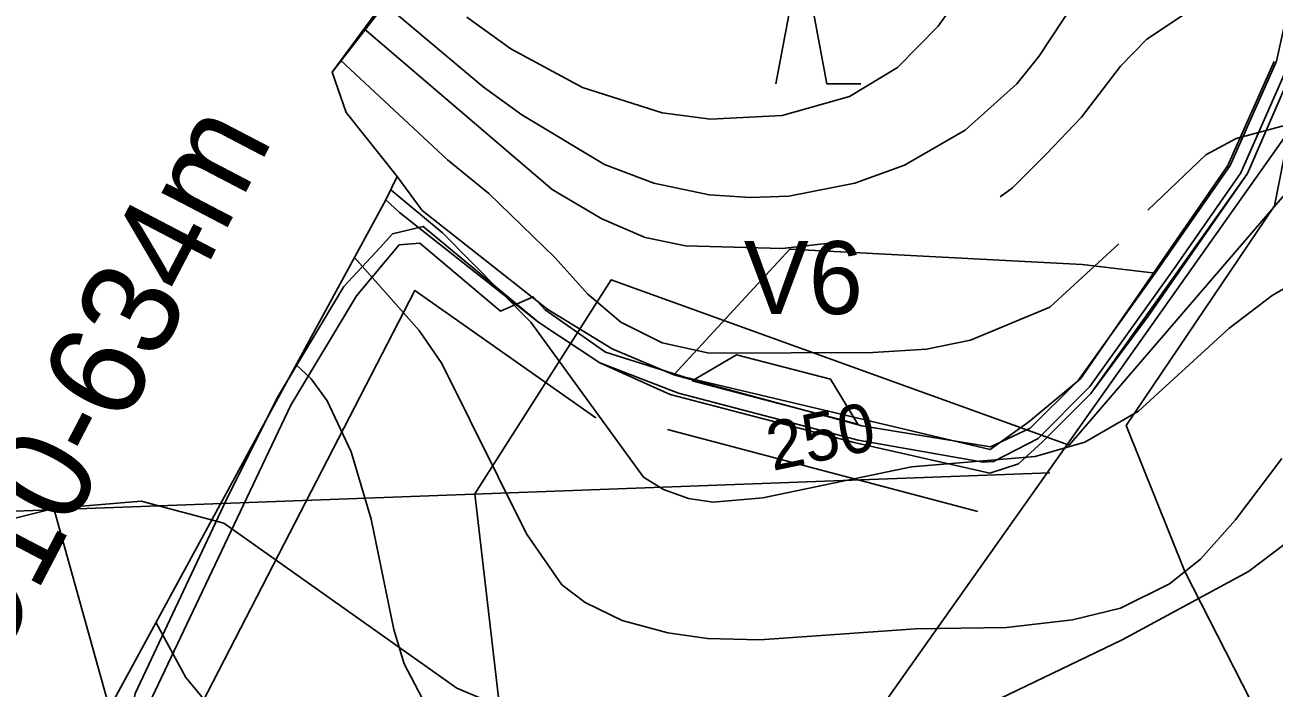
# Model space of a CAD drawing. Extents: x -662500 to -653478, y -1056827 to -1049993.
# Drawn here: x -659945.9 to -659688.8, y -1052338.9 to -1052202.5 of the extents above; entities that cross this region are included whole.
import ezdxf

# ---------------------------------------------------------------- set-up
doc = ezdxf.new("R2010")
doc.units = 0
for name, color, linetype in [('Vrstva 1', 7, 'Continuous'), ('Vrstva 11', 7, 'Continuous'), ('Vrstva 18', 7, 'Continuous'), ('Vrstva 24', 7, 'Continuous'), ('Vrstva 36', 7, 'Continuous'), ('Vrstva 37', 7, 'Continuous'), ('Vrstva 44', 7, 'Continuous'), ('Vrstva 5', 7, 'Continuous'), ('Vrstva 54', 7, 'Continuous'), ('Vrstva 61', 7, 'Continuous'), ('Vrstva 7', 7, 'Continuous'), ('Vrstva 9', 7, 'Continuous')]:
    doc.layers.add(name, color=color, linetype=linetype)

msp = doc.modelspace()

# ---------------------------------------------------------------- linework, layer by layer
at = {"layer": 'Vrstva 1'}
msp.add_lwpolyline([(-659675.39, -1052019.4), (-659639.54, -1052020.88), (-659636.44, -1052033.86), (-659626.36, -1052069.96), (-659618.18, -1052102.6), (-659620.12, -1052107.5), (-659721.07, -1052150.88), (-659741.57, -1052138.62), (-659753.8, -1052131.2), (-659796, -1052100.66), (-659846.91, -1052165.44), (-659851.91, -1052171.69), (-659862.84, -1052185.26), (-659882.68, -1052212.21), (-659879.78, -1052220.54), (-659869.29, -1052233.66), (-659871.6, -1052238.48), (-659931.31, -1052348.25), (-659940.37, -1052344.82), (-659945.94, -1052342.8), (-659950.73, -1052341.07)], dxfattribs=at)
at = {"layer": 'Vrstva 11'}
msp.add_lwpolyline([(-659917.49, -1052397.56), (-659924.78, -1052366.68), (-659925.74, -1052353.85), (-659923.21, -1052340.09), (-659904.49, -1052300.27), (-659893.99, -1052279.25), (-659880.31, -1052256.29), (-659872.77, -1052248.3), (-659870.23, -1052245.5), (-659863.95, -1052244.01), (-659853.1, -1052252.98), (-659840.13, -1052263.76), (-659827.56, -1052272.06), (-659811.34, -1052278.29), (-659774.4, -1052287.97), (-659748.64, -1052292.5), (-659746.51, -1052292.32), (-659737.34, -1052287.62), (-659726.66, -1052276.92), (-659709.46, -1052252.85), (-659695.61, -1052232.91), (-659685.89, -1052211.02)], dxfattribs=at)
at = {"layer": 'Vrstva 24'}
for points in [[(-659753.8, -1052131.2), (-659796, -1052100.66), (-659846.91, -1052165.44), (-659851.91, -1052171.69), (-659862.84, -1052185.26), (-659882.68, -1052212.21), (-659879.78, -1052220.54), (-659869.29, -1052233.66), (-659864.18, -1052240.66), (-659838.29, -1052261.09), (-659825.01, -1052269.17), (-659812.36, -1052274.48), (-659788.46, -1052248.64), (-659728.23, -1052251.8), (-659713.25, -1052253.61), (-659697.8, -1052231.4), (-659688.24, -1052209.97)], [(-659443, -1052294), (-659507.5, -1052284.5), (-659587, -1052268), (-659607.5, -1052267.5), (-659628.5, -1052271), (-659641, -1052276), (-659667, -1052294.5), (-659694, -1052315), (-659720, -1052329), (-659747, -1052342), (-659770.5, -1052347.5), (-659807.5, -1052352.5), (-659839, -1052346.5), (-659857, -1052339), (-659905, -1052305), (-659922, -1052300.5), (-659940, -1052302)], [(-659940, -1052302), (-659996, -1052316), (-660000, -1052315.12), (-660048, -1052304.5)], [(-660034, -1052954), (-660032, -1052948.5), (-660000, -1052906.38), (-659983, -1052884), (-659923.5, -1052843.5), (-659891.5, -1052807.5), (-659876.5, -1052780.5), (-659868, -1052749), (-659871, -1052717.5), (-659880, -1052690.5), (-659893, -1052641), (-659893, -1052609.5), (-659864.5, -1052533), (-659861.5, -1052506), (-659866.5, -1052474.5), (-659880.5, -1052438.5), (-659901.5, -1052398), (-659927, -1052348.5), (-659940, -1052302)]]:
    msp.add_lwpolyline(points, dxfattribs=at)
at = {"layer": 'Vrstva 36'}
msp.add_lwpolyline([(-659390.32, -1052019.34), (-659473.97, -1052032.46), (-659523.65, -1052033.38), (-659629.9, -1052027.09), (-659621.04, -1052067.57), (-659612.63, -1052095.78), (-659613.06, -1052104.19), (-659616.18, -1052110.87), (-659620.93, -1052116.23), (-659629.5, -1052120.84), (-659671.87, -1052141.1), (-659688.36, -1052149.79), (-659691.31, -1052152.96), (-659692.79, -1052159.14), (-659681.03, -1052192.1), (-659680.96, -1052200.79), (-659688.64, -1052239.7), (-659719.21, -1052284.92), (-659707.09, -1052314.99), (-659690.29, -1052347.87), (-659666.49, -1052401.44), (-659649.62, -1052458.41), (-659626.31, -1052501.42), (-659596.35, -1052541.51)], dxfattribs=at)
at = {"layer": 'Vrstva 37'}
msp.add_lwpolyline([(-659673.12, -1052221.79), (-659730.97, -1052288.96), (-659825.23, -1052254.93), (-659853.32, -1052299.01), (-659834.91, -1052457.14), (-659834.91, -1052490), (-659853.87, -1052611.9), (-659835.65, -1052648.36), (-659788.97, -1052656.33), (-659725.21, -1052638.68), (-659681.94, -1052610.76)], dxfattribs=at)
at = {"layer": 'Vrstva 44'}
msp.add_line((-659734.95, -1052294.69), (-659980.47, -1052303.77), dxfattribs=at)
msp.add_lwpolyline([(-659464.58, -1051504.83), (-659576.16, -1052069.59), (-659916.29, -1052550.1), (-660191.14, -1052457.81)], dxfattribs=at)
at = {"layer": 'Vrstva 5'}
msp.add_lwpolyline([(-659729.06, -1052275.65), (-659738.99, -1052285.45), (-659747.16, -1052289.35), (-659773.64, -1052284.97), (-659812.36, -1052274.48), (-659825.01, -1052269.17), (-659838.29, -1052261.09), (-659864.18, -1052240.66), (-659869.29, -1052233.66), (-659879.78, -1052220.54), (-659882.68, -1052212.21), (-659796, -1052100.66), (-659753.8, -1052131.2), (-659721.07, -1052150.88), (-659711.91, -1052164.91), (-659709.2, -1052168.26), (-659686.18, -1052192.72), (-659686.02, -1052200.03), (-659688.24, -1052209.98), (-659697.8, -1052231.4), (-659713.25, -1052253.61)], close=True, dxfattribs=at)
for points in [[(-659688.24, -1052209.98), (-659697.8, -1052231.4), (-659713.25, -1052253.61), (-659729.06, -1052275.65), (-659738.99, -1052285.45), (-659747.16, -1052289.35), (-659773.64, -1052284.97), (-659812.36, -1052274.48), (-659825.01, -1052269.17), (-659838.29, -1052261.09), (-659864.18, -1052240.66), (-659869.29, -1052233.66), (-659871.6, -1052238.48), (-659868.79, -1052241.13), (-659840.13, -1052263.76), (-659827.56, -1052272.06), (-659813.08, -1052278.54), (-659775.22, -1052288.4), (-659747.24, -1052294.73), (-659741.36, -1052292.78), (-659736.43, -1052288.26), (-659726.46, -1052278.31), (-659694.22, -1052233.07), (-659686.06, -1052214.27)], [(-659686.06, -1052214.27), (-659694.22, -1052233.07), (-659714.68, -1052262.41), (-659726.46, -1052278.31), (-659736.43, -1052288.26), (-659741.36, -1052292.78), (-659747.24, -1052294.73), (-659775.22, -1052288.4), (-659813.08, -1052278.54), (-659827.56, -1052272.06), (-659840.13, -1052263.76), (-659868.79, -1052241.13), (-659871.6, -1052238.48), (-659931.31, -1052348.25), (-659943.97, -1052343.51), (-659933.07, -1052386.77), (-659931.7, -1052394.49), (-659546.84, -1052563.39)]]:
    msp.add_lwpolyline(points, dxfattribs=at)
at = {"layer": 'Vrstva 54'}
msp.add_line((-659813.63, -1052285.77), (-659749.72, -1052302.65), dxfattribs=at)
msp.add_lwpolyline([(-659910.52, -1052384.29), (-659910.52, -1052344.09), (-659865.63, -1052257.13), (-659828.38, -1052283.35)], dxfattribs=at)
at = {"layer": 'Vrstva 61'}
msp.add_lwpolyline([(-659688.75, -1052210.04), (-659698.25, -1052231.42), (-659728.58, -1052275.29), (-659739.22, -1052284.17), (-659747.21, -1052289.87), (-659810.05, -1052275), (-659826.41, -1052269.83), (-659838.84, -1052261.15), (-659841.31, -1052258.43), (-659848, -1052261.39), (-659864.6, -1052247.41), (-659868.9, -1052247.76), (-659877.7, -1052258.26), (-659891.18, -1052280.74), (-659919.74, -1052340.82), (-659922.59, -1052354.12), (-659921.7, -1052366.31), (-659914.24, -1052395.35), (-659922.44, -1052390.4)], dxfattribs=at)
msp.add_lwpolyline([(-659808.56, -1052275.72), (-659799.4, -1052270.36), (-659780.05, -1052275.42), (-659774.44, -1052284.64)], close=True, dxfattribs=at)
at = {"layer": 'Vrstva 7'}
for p, q in [((-659750.81, -1052192.83), (-659757.89, -1052202.75)), ((-659851.57, -1052215.22), (-659872.2, -1052197.98)), ((-659729.69, -1052197.65), (-659737.2, -1052208.99)), ((-659845.9, -1052207.43), (-659854.97, -1052200.91)), ((-659705.32, -1052199.06), (-659714.95, -1052205.44)), ((-659837.4, -1052236.34), (-659876.11, -1052203.28)), ((-659757.89, -1052202.75), (-659766.25, -1052211.25)), ((-659714.95, -1052205.44), (-659720.34, -1052210.97)), ((-659831.16, -1052215.36), (-659845.9, -1052207.43)), ((-659737.2, -1052208.99), (-659741.74, -1052214.65)), ((-659858.94, -1052230.24), (-659880.92, -1052209.82)), ((-659766.25, -1052211.25), (-659776.17, -1052217.2)), ((-659720.34, -1052210.97), (-659728.42, -1052221.46)), ((-659843.63, -1052221.03), (-659851.57, -1052215.22)), ((-659814.72, -1052220.6), (-659831.16, -1052215.36)), ((-659741.74, -1052214.65), (-659752.37, -1052224.15)), ((-659776.17, -1052217.2), (-659790.06, -1052221.17)), ((-659826.62, -1052231.23), (-659843.63, -1052221.03)), ((-659804.8, -1052221.88), (-659814.72, -1052220.6)), ((-659790.06, -1052221.17), (-659804.8, -1052221.88)), ((-659728.42, -1052221.46), (-659735.64, -1052229.11)), ((-659752.37, -1052224.15), (-659764.84, -1052231.38)), ((-659686.33, -1052223.16), (-659696.53, -1052225.85)), ((-659696.53, -1052225.85), (-659702.77, -1052229.25)), ((-659735.64, -1052229.11), (-659742.61, -1052236.05)), ((-659702.77, -1052229.25), (-659714.73, -1052240.59)), ((-659850.43, -1052237.19), (-659858.94, -1052230.24)), ((-659816.42, -1052235.06), (-659826.62, -1052231.23)), ((-659764.84, -1052231.38), (-659775.04, -1052235.06)), ((-659859.93, -1052245.26), (-659870.62, -1052236.43)), ((-659836.83, -1052250.37), (-659850.43, -1052237.19)), ((-659827.19, -1052242.43), (-659837.4, -1052236.34)), ((-659805.08, -1052237.47), (-659816.42, -1052235.06)), ((-659775.04, -1052235.06), (-659788.65, -1052237.75)), ((-659742.61, -1052236.05), (-659745.12, -1052237.85)), ((-659796.58, -1052238.04), (-659805.08, -1052237.47)), ((-659788.65, -1052237.75), (-659796.58, -1052238.04)), ((-659818.26, -1052246.26), (-659827.19, -1052242.43)), ((-659841.79, -1052263.69), (-659859.93, -1052245.26)), ((-659809.9, -1052247.96), (-659818.26, -1052246.26)), ((-659778.49, -1052247.18), (-659790.06, -1052248.52)), ((-659720.72, -1052247.54), (-659734.93, -1052260.57)), ((-659790.06, -1052248.52), (-659809.9, -1052247.96)), ((-659864.75, -1052265.39), (-659878.05, -1052250.33)), ((-659830.03, -1052257.88), (-659836.83, -1052250.37)), ((-659679.24, -1052252.35), (-659689.16, -1052258.16)), ((-659823.22, -1052263.69), (-659830.03, -1052257.88)), ((-659689.16, -1052258.16), (-659698.09, -1052264.96)), ((-659734.93, -1052260.57), (-659751.23, -1052267.37)), ((-659860.07, -1052272.19), (-659864.75, -1052265.39)), ((-659818.55, -1052295.57), (-659841.79, -1052263.69)), ((-659814.72, -1052267.94), (-659823.22, -1052263.69)), ((-659698.09, -1052264.96), (-659716.65, -1052281.97)), ((-659805.08, -1052270.06), (-659814.72, -1052267.94)), ((-659751.23, -1052267.37), (-659760.3, -1052269.21)), ((-659771.36, -1052269.92), (-659805.08, -1052270.06)), ((-659760.3, -1052269.21), (-659771.36, -1052269.92)), ((-659887, -1052275.31), (-659890.07, -1052272.44)), ((-659842.64, -1052307.19), (-659860.07, -1052272.19)), ((-659883.74, -1052279.84), (-659887, -1052275.31)), ((-659878.78, -1052290.33), (-659883.74, -1052279.84)), ((-659716.65, -1052281.97), (-659727.71, -1052288.35)), ((-659727.71, -1052288.35), (-659737.91, -1052291.32)), ((-659874.67, -1052304.22), (-659878.78, -1052290.33)), ((-659737.91, -1052291.32), (-659763.42, -1052293.45)), ((-659763.42, -1052293.45), (-659794.03, -1052299.82)), ((-659687.18, -1052291.75), (-659696.67, -1052304.36)), ((-659814.44, -1052298.12), (-659818.55, -1052295.57)), ((-659809.34, -1052299.97), (-659814.44, -1052298.12)), ((-659804.23, -1052300.68), (-659809.34, -1052299.97)), ((-659794.03, -1052299.82), (-659804.23, -1052300.68)), ((-659869.99, -1052326.89), (-659874.67, -1052304.22)), ((-659696.67, -1052304.36), (-659703.9, -1052312.44)), ((-659835.41, -1052317.68), (-659842.64, -1052307.19)), ((-659703.9, -1052312.44), (-659710.28, -1052317.54)), ((-659830.59, -1052321.37), (-659835.41, -1052317.68)), ((-659710.28, -1052317.54), (-659720.34, -1052322.5)), ((-659822.94, -1052325.05), (-659830.59, -1052321.37)), ((-659720.34, -1052322.5), (-659730.26, -1052324.91)), ((-659912.79, -1052336.81), (-659918.94, -1052325.51)), ((-659867.86, -1052333.98), (-659869.99, -1052326.89)), ((-659813.59, -1052327.6), (-659822.94, -1052325.05)), ((-659762.57, -1052326.75), (-659794.6, -1052329.02)), ((-659743.86, -1052326.47), (-659762.57, -1052326.75)), ((-659730.26, -1052324.91), (-659743.86, -1052326.47)), ((-659805.37, -1052328.74), (-659813.59, -1052327.6)), ((-659794.6, -1052329.02), (-659805.37, -1052328.74)), ((-659863.47, -1052342.34), (-659867.86, -1052333.98)), ((-659904.14, -1052347.16), (-659912.79, -1052336.81))]:
    msp.add_line(p, q, dxfattribs=at)
at = {"layer": 'Vrstva 9'}
msp.add_lwpolyline([(-659791.31, -1052214.64), (-659786.06, -1052186.64), (-659780.81, -1052214.64), (-659773.81, -1052214.64)], dxfattribs=at)

# ---------------------------------------------------------------- texts
at = {"layer": 'Vrstva 18'}
msp.add_text('C10-634m', height=20, rotation=62.4394, dxfattribs=at).set_placement((-659952.52, -1052336.71))
at = {"layer": 'Vrstva 61'}
msp.add_text('V6', height=15, dxfattribs=at).set_placement((-659797.93, -1052261.99))
at = {"layer": 'Vrstva 7'}
msp.add_text('250', height=10, rotation=11.7681, dxfattribs=at).set_placement((-659792.03, -1052294.3))

doc.saveas('drawing.dxf')
